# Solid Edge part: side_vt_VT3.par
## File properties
Author: haileyy
Template: ansi part.par
Last saved by: harmonj5
Revision: 6
Application: Solid Edge
Accuracy: 0.990
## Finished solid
Body 1: solid body, 63 faces, 183 edges, 122 vertices.
  Faces by surface: plane 36, cylinder 19, swept 8
  Edges by curve: line 129, circle 38, spline 16
Bounding box of the edges (mm; curved faces can reach further): 187.481 x 22.561 x 3.175, from (-219.7328, -38.0401, -3.175) to (-32.2514, -15.4793, 0).
Cylindrical faces by radius (mm): R1.5875 x1, R3.175 x10, R16.9944 x1, R31.0281 x1, R134.692 x1, R143.1992 x1, R182.8394 x1, R277.883 x1, R894.7382 x2
Planar faces by outward normal: +x 9, +y 5, +z 1, -x 8, -y 5, -z 1, oblique 7
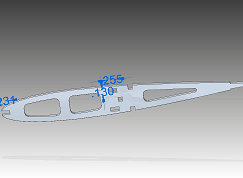
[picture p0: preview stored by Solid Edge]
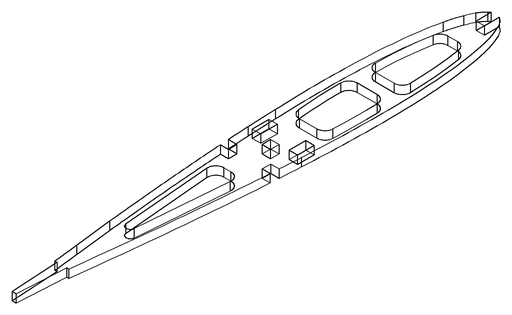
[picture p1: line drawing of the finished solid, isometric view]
